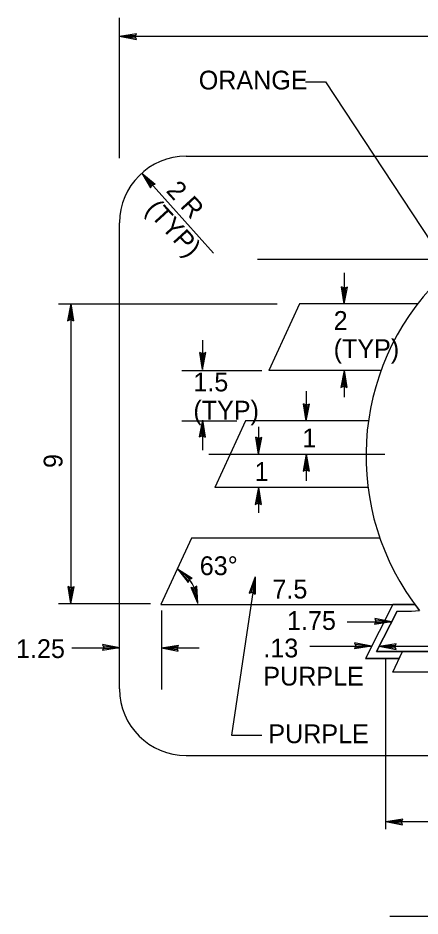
# Model space of a CAD drawing. Extents: x 10268197 to 10269179, y 2141503 to 2142677.
# Drawn here: x 10268780.26 to 10268795.36, y 2142016.12 to 2142049.83 of the extents above; entities that cross this region are included whole.
import ezdxf

# ---------------------------------------------------------------- set-up
doc = ezdxf.new("R2010")
doc.units = 0
for name, color, linetype in [('1', 7, 'Continuous'), ('21', 7, 'Continuous'), ('Default', 7, 'Continuous'), ('TextMisc', 7, 'Continuous'), ('TextShtNo', 7, 'Continuous')]:
    doc.layers.add(name, color=color, linetype=linetype)

msp = doc.modelspace()

# ---------------------------------------------------------------- linework, layer by layer
at = {"layer": '1'}
for p, q in [((10268784.913, 2142044.011), (10268787.598, 2142041.004)), ((10268789.17, 2142028.852), (10268788.281, 2142022.913)), ((10268794.575, 2142025.792), (10268793.308, 2142025.792)), ((10268788.281, 2142022.913), (10268789.414, 2142022.913))]:
    msp.add_line(p, q, dxfattribs=at)
msp.add_ellipse((10268785.52, 2142027.836), major_axis=(0, 1.49), ratio=0.999997, start_param=4.726798, end_param=5.778675, dxfattribs=at)
at = {"layer": '21'}
msp.add_line((10268794.221, 2142016.121), (10268803.934, 2142016.121), dxfattribs=at)
at = {"layer": 'Default'}
for p, q in [((10268784.077, 2142049.15), (10268784.717, 2142049.251)), ((10268784.077, 2142049.15), (10268784.69, 2142049.193)), ((10268784.077, 2142049.15), (10268814.077, 2142049.15)), ((10268784.077, 2142049.15), (10268784.713, 2142049.026)), ((10268784.077, 2142049.15), (10268784.689, 2142049.086)), ((10268784.666, 2142049.139), (10268784.717, 2142049.251)), ((10268784.713, 2142049.026), (10268784.666, 2142049.139)), ((10268791.052, 2142047.436), (10268791.809, 2142047.436)), ((10268791.809, 2142047.436), (10268796.919, 2142039.671)), ((10268786.578, 2142044.646), (10268811.577, 2142044.646)), ((10268784.913, 2142044.011), (10268785.414, 2142043.601)), ((10268784.913, 2142044.011), (10268785.244, 2142043.455)), ((10268784.913, 2142044.011), (10268785.272, 2142043.512)), ((10268784.913, 2142044.011), (10268785.352, 2142043.583)), ((10268785.244, 2142043.455), (10268785.297, 2142043.565)), ((10268785.297, 2142043.565), (10268785.414, 2142043.601)), ((10268784.077, 2142024.646), (10268784.077, 2142042.146)), ((10268789.255, 2142040.78), (10268800.592, 2142040.78)), ((10268792.511, 2142040.267), (10268792.511, 2142039.099)), ((10268792.511, 2142039.099), (10268792.41, 2142039.738)), ((10268792.521, 2142039.687), (10268792.41, 2142039.738)), ((10268792.511, 2142039.099), (10268792.468, 2142039.711)), ((10268792.511, 2142039.099), (10268792.634, 2142039.734)), ((10268792.511, 2142039.099), (10268792.575, 2142039.71)), ((10268792.634, 2142039.734), (10268792.521, 2142039.687)), ((10268781.792, 2142039.099), (10268789.999, 2142039.099)), ((10268782.245, 2142039.099), (10268782.122, 2142038.463)), ((10268782.245, 2142039.099), (10268782.181, 2142038.487)), ((10268782.245, 2142039.099), (10268782.245, 2142027.848)), ((10268782.245, 2142039.099), (10268782.346, 2142038.459)), ((10268782.245, 2142039.099), (10268782.288, 2142038.486)), ((10268790.836, 2142039.099), (10268789.681, 2142036.599)), ((10268795.261, 2142039.099), (10268790.836, 2142039.099)), ((10268782.122, 2142038.463), (10268782.235, 2142038.51)), ((10268782.235, 2142038.51), (10268782.346, 2142038.459)), ((10268787.191, 2142037.744), (10268787.191, 2142036.635)), ((10268787.191, 2142036.635), (10268787.09, 2142037.274)), ((10268787.201, 2142037.223), (10268787.09, 2142037.274)), ((10268787.191, 2142036.635), (10268787.148, 2142037.247)), ((10268787.191, 2142036.635), (10268787.314, 2142037.271)), ((10268787.191, 2142036.635), (10268787.254, 2142037.246)), ((10268787.314, 2142037.271), (10268787.201, 2142037.223)), ((10268786.411, 2142036.599), (10268789.417, 2142036.599)), ((10268793.891, 2142036.599), (10268789.681, 2142036.599)), ((10268792.511, 2142036.599), (10268792.388, 2142035.963)), ((10268792.511, 2142036.599), (10268792.447, 2142035.987)), ((10268792.511, 2142036.599), (10268792.511, 2142035.593)), ((10268792.511, 2142036.599), (10268792.613, 2142035.959)), ((10268792.511, 2142036.599), (10268792.554, 2142035.986)), ((10268792.388, 2142035.963), (10268792.501, 2142036.01)), ((10268792.501, 2142036.01), (10268792.613, 2142035.959)), ((10268791.087, 2142035.821), (10268791.087, 2142034.705)), ((10268791.087, 2142034.705), (10268790.985, 2142035.344)), ((10268791.097, 2142035.294), (10268790.985, 2142035.344)), ((10268791.087, 2142034.705), (10268791.044, 2142035.317)), ((10268791.087, 2142034.705), (10268791.21, 2142035.34)), ((10268791.087, 2142034.705), (10268791.151, 2142035.316)), ((10268791.21, 2142035.34), (10268791.097, 2142035.294)), ((10268786.411, 2142034.705), (10268788.478, 2142034.705)), ((10268787.191, 2142034.74), (10268787.068, 2142034.104)), ((10268787.191, 2142034.74), (10268787.127, 2142034.129)), ((10268787.191, 2142034.74), (10268787.191, 2142033.61)), ((10268787.191, 2142034.74), (10268787.292, 2142034.1)), ((10268787.191, 2142034.74), (10268787.234, 2142034.127)), ((10268788.807, 2142034.705), (10268787.652, 2142032.205)), ((10268793.419, 2142034.705), (10268788.807, 2142034.705)), ((10268789.292, 2142034.482), (10268789.292, 2142033.455)), ((10268787.068, 2142034.104), (10268787.18, 2142034.151)), ((10268787.18, 2142034.151), (10268787.292, 2142034.1)), ((10268789.292, 2142033.455), (10268789.191, 2142034.094)), ((10268789.302, 2142034.044), (10268789.191, 2142034.094)), ((10268789.292, 2142033.455), (10268789.249, 2142034.067)), ((10268789.292, 2142033.455), (10268789.415, 2142034.091)), ((10268789.292, 2142033.455), (10268789.356, 2142034.066)), ((10268789.415, 2142034.091), (10268789.302, 2142034.044)), ((10268787.432, 2142033.455), (10268794.029, 2142033.455)), ((10268791.087, 2142033.455), (10268790.964, 2142032.819)), ((10268791.087, 2142033.455), (10268791.023, 2142032.843)), ((10268791.087, 2142033.455), (10268791.087, 2142032.458)), ((10268791.087, 2142033.455), (10268791.188, 2142032.816)), ((10268791.087, 2142033.455), (10268791.13, 2142032.842)), ((10268790.964, 2142032.819), (10268791.077, 2142032.866)), ((10268791.077, 2142032.866), (10268791.188, 2142032.816)), ((10268793.404, 2142032.205), (10268787.652, 2142032.205)), ((10268789.292, 2142032.205), (10268789.169, 2142031.569)), ((10268789.292, 2142032.205), (10268789.228, 2142031.593)), ((10268789.292, 2142032.205), (10268789.292, 2142031.261)), ((10268789.292, 2142032.205), (10268789.393, 2142031.565)), ((10268789.292, 2142032.205), (10268789.335, 2142031.592)), ((10268789.169, 2142031.569), (10268789.282, 2142031.616)), ((10268789.282, 2142031.616), (10268789.393, 2142031.565)), ((10268786.777, 2142030.31), (10268785.627, 2142027.821)), ((10268793.826, 2142030.31), (10268786.777, 2142030.31)), ((10268786.249, 2142029.15), (10268786.799, 2142028.808)), ((10268786.249, 2142029.15), (10268786.649, 2142028.641)), ((10268786.249, 2142029.15), (10268786.669, 2142028.702)), ((10268786.249, 2142029.15), (10268786.74, 2142028.782)), ((10268786.687, 2142028.757), (10268786.799, 2142028.808)), ((10268789.17, 2142028.852), (10268788.944, 2142028.245)), ((10268789.17, 2142028.852), (10268789.007, 2142028.26)), ((10268789.17, 2142028.852), (10268789.112, 2142028.241)), ((10268789.17, 2142028.852), (10268789.165, 2142028.204)), ((10268782.245, 2142027.848), (10268782.144, 2142028.488)), ((10268782.255, 2142028.437), (10268782.144, 2142028.488)), ((10268782.245, 2142027.848), (10268782.368, 2142028.484)), ((10268782.368, 2142028.484), (10268782.255, 2142028.437)), ((10268786.649, 2142028.641), (10268786.687, 2142028.757)), ((10268786.978, 2142028.508), (10268786.88, 2142028.434)), ((10268787.021, 2142027.861), (10268786.926, 2142028.468)), ((10268787.021, 2142027.861), (10268786.978, 2142028.508)), ((10268782.245, 2142027.848), (10268782.202, 2142028.461)), ((10268782.245, 2142027.848), (10268782.308, 2142028.46)), ((10268787.021, 2142027.861), (10268786.759, 2142028.454)), ((10268786.88, 2142028.434), (10268786.759, 2142028.454)), ((10268787.021, 2142027.861), (10268786.823, 2142028.443)), ((10268788.944, 2142028.245), (10268789.063, 2142028.273)), ((10268789.063, 2142028.273), (10268789.165, 2142028.204)), ((10268781.792, 2142027.848), (10268785.241, 2142027.848)), ((10268785.627, 2142027.821), (10268795.145, 2142027.821)), ((10268794.34, 2142027.821), (10268793.308, 2142025.792)), ((10268794.34, 2142027.821), (10268795.169, 2142027.821)), ((10268785.646, 2142027.585), (10268785.646, 2142024.62)), ((10268794.495, 2142027.567), (10268793.722, 2142026.046)), ((10268794.496, 2142027.567), (10268795.029, 2142027.567)), ((10268795.029, 2142027.567), (10268795.34, 2142027.591)), ((10268792.622, 2142027.162), (10268794.29, 2142027.162)), ((10268793.701, 2142027.172), (10268793.65, 2142027.061)), ((10268794.29, 2142027.162), (10268793.65, 2142027.061)), ((10268794.29, 2142027.162), (10268793.654, 2142027.285)), ((10268793.654, 2142027.285), (10268793.701, 2142027.172)), ((10268794.29, 2142027.162), (10268793.678, 2142027.226)), ((10268794.29, 2142027.162), (10268793.678, 2142027.119)), ((10268782.288, 2142026.19), (10268784.077, 2142026.19)), ((10268783.489, 2142026.2), (10268783.438, 2142026.089)), ((10268784.077, 2142026.19), (10268783.438, 2142026.089)), ((10268784.077, 2142026.19), (10268783.442, 2142026.313)), ((10268783.442, 2142026.313), (10268783.489, 2142026.2)), ((10268784.077, 2142026.19), (10268783.465, 2142026.147)), ((10268784.077, 2142026.19), (10268783.466, 2142026.254)), ((10268785.646, 2142026.19), (10268786.285, 2142026.291)), ((10268785.646, 2142026.19), (10268786.258, 2142026.233)), ((10268785.646, 2142026.19), (10268787.062, 2142026.19)), ((10268785.646, 2142026.19), (10268786.281, 2142026.067)), ((10268785.646, 2142026.19), (10268786.257, 2142026.127)), ((10268786.235, 2142026.18), (10268786.285, 2142026.291)), ((10268786.281, 2142026.067), (10268786.235, 2142026.18)), ((10268791.215, 2142026.248), (10268793.535, 2142026.248)), ((10268792.946, 2142026.258), (10268792.895, 2142026.147)), ((10268793.535, 2142026.248), (10268792.895, 2142026.147)), ((10268793.535, 2142026.248), (10268792.899, 2142026.371)), ((10268792.899, 2142026.371), (10268792.946, 2142026.258)), ((10268793.535, 2142026.248), (10268792.923, 2142026.205)), ((10268793.535, 2142026.248), (10268792.924, 2142026.311)), ((10268793.819, 2142026.248), (10268794.459, 2142026.349)), ((10268793.819, 2142026.248), (10268794.432, 2142026.291)), ((10268793.819, 2142026.248), (10268795.727, 2142026.248)), ((10268793.819, 2142026.248), (10268794.455, 2142026.125)), ((10268793.819, 2142026.248), (10268794.43, 2142026.184)), ((10268794.408, 2142026.238), (10268794.459, 2142026.349)), ((10268794.455, 2142026.125), (10268794.408, 2142026.238)), ((10268793.722, 2142026.046), (10268794.816, 2142026.046)), ((10268794.066, 2142019.382), (10268794.066, 2142025.804)), ((10268794.335, 2142025.27), (10268794.692, 2142026.046)), ((10268805.941, 2142026.046), (10268794.692, 2142026.046)), ((10268806.635, 2142025.27), (10268794.335, 2142025.27)), ((10268786.578, 2142022.146), (10268811.577, 2142022.146)), ((10268794.066, 2142019.672), (10268794.706, 2142019.773)), ((10268794.066, 2142019.672), (10268794.679, 2142019.715)), ((10268794.655, 2142019.662), (10268794.706, 2142019.773)), ((10268794.066, 2142019.672), (10268805.941, 2142019.672)), ((10268794.066, 2142019.672), (10268794.702, 2142019.549)), ((10268794.066, 2142019.672), (10268794.677, 2142019.608)), ((10268794.702, 2142019.549), (10268794.655, 2142019.662))]:
    msp.add_line(p, q, dxfattribs=at)
msp.add_lwpolyline([(10268795.169, 2142027.821), (10268794.34, 2142027.821), (10268793.308, 2142025.792), (10268794.575, 2142025.792), (10268794.692, 2142026.046), (10268793.722, 2142026.046), (10268794.496, 2142027.567), (10268795.029, 2142027.567), (10268795.34, 2142027.591)], close=True, dxfattribs=at)
for centre, major_axis, start_param, end_param in [((10268786.577, 2142042.146), (0, 2.5), 0, 1.570796), ((10268802.702, 2142033.396), (0, 9.375), 5.619293, 8.52162), ((10268786.577, 2142024.646), (0, -2.5), 4.712389, 6.283185)]:
    msp.add_ellipse(centre, major_axis=major_axis, ratio=0.999997, start_param=start_param, end_param=end_param, dxfattribs=at)
at = {"layer": 'TextMisc'}
msp.add_line((10268784.077, 2142044.576), (10268784.077, 2142049.834), dxfattribs=at)
at = {"layer": 'TextShtNo'}
for p, q in [((10268794.335, 2142025.27), (10268794.692, 2142026.046)), ((10268794.692, 2142026.046), (10268805.941, 2142026.046)), ((10268806.635, 2142025.27), (10268794.335, 2142025.27))]:
    msp.add_line(p, q, dxfattribs=at)

# ---------------------------------------------------------------- texts
at = {"layer": '1'}
for s, height, p in [('ORANGE', 0.7047, (10268787.05, 2142047.15)), ('2', 0.705, (10268792.113, 2142038.125)), ('(TYP)', 0.7047, (10268792.113, 2142037.068)), ('1.5', 0.7047, (10268786.848, 2142035.816)), ('(TYP)', 0.7047, (10268786.848, 2142034.759)), ('1', 0.705, (10268790.94, 2142033.715)), ('1', 0.705, (10268789.146, 2142032.455)), ('63°', 0.7047, (10268787.087, 2142028.919)), ('7.5', 0.7047, (10268789.815, 2142028.039)), ('1.75', 0.7047, (10268790.364, 2142026.862)), ('1.25', 0.7047, (10268780.193, 2142025.807)), ('.13', 0.7047, (10268789.475, 2142025.83)), ('PURPLE', 0.7047, (10268789.475, 2142024.773)), ('PURPLE', 0.7047, (10268789.662, 2142022.61))]:
    msp.add_text(s, height=height, dxfattribs=at).set_placement(p)
for s, height, rotation, p in [('2 R', 0.7047, 312.435, (10268785.793, 2142043.327)), ('(TYP)', 0.7047, 312.435, (10268785.013, 2142042.614)), ('9', 0.705, 90, (10268781.935, 2142032.94))]:
    msp.add_text(s, height=height, rotation=rotation, dxfattribs=at).set_placement(p)

doc.saveas('drawing.dxf')
